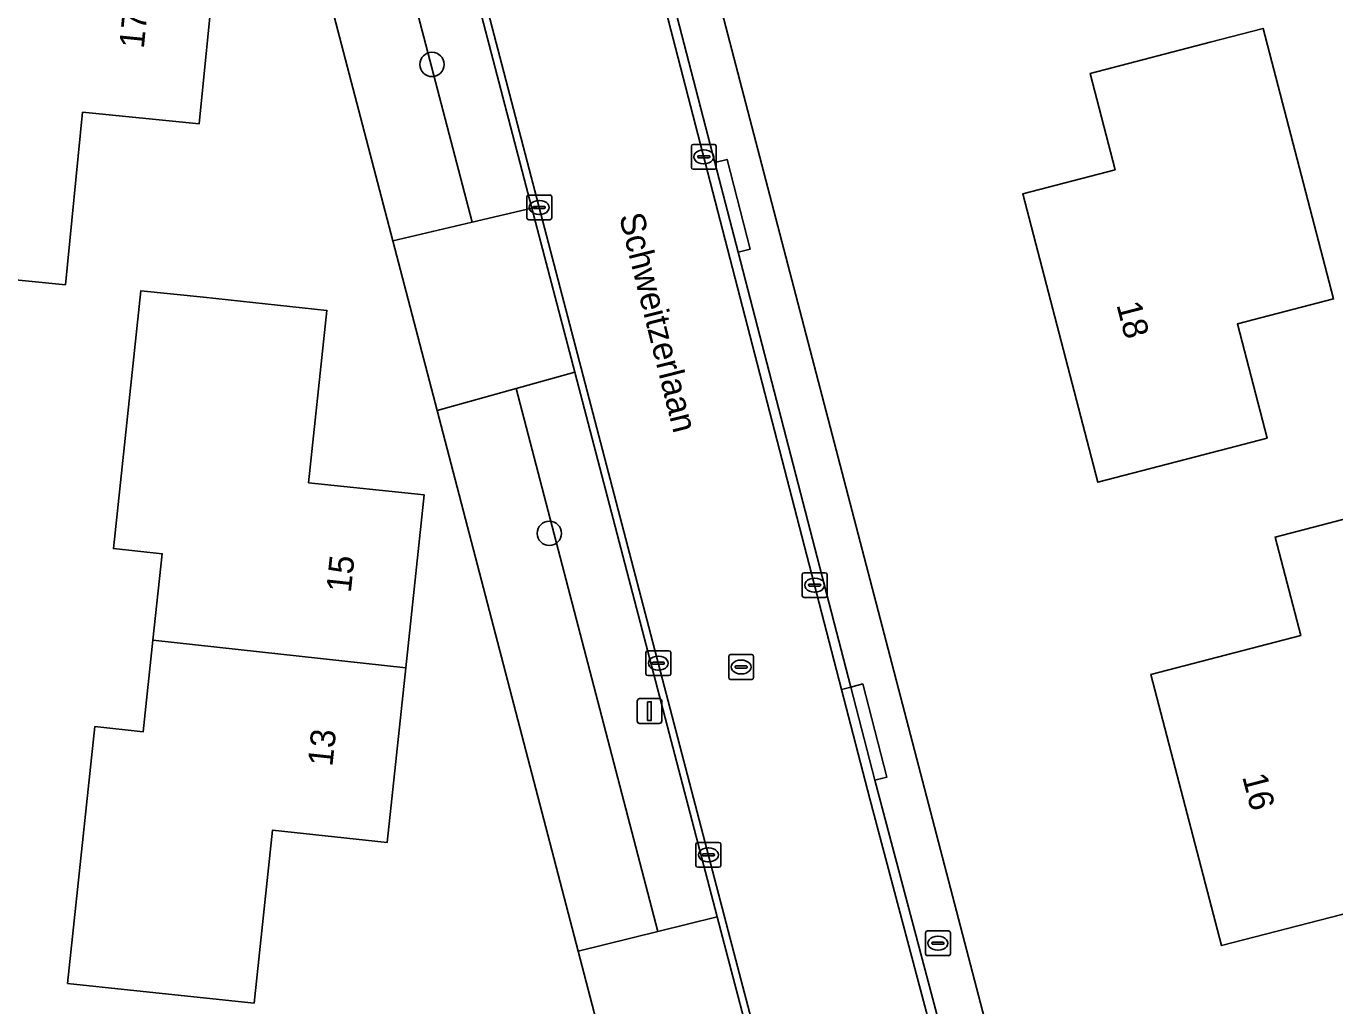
# Model space of a CAD drawing. Extents: x 162156 to 163172, y 378995 to 380779.
# Drawn here: x 162675 to 162727.7, y 380333.8 to 380373.3 of the extents above; entities that cross this region are included whole.
import ezdxf

# ---------------------------------------------------------------- set-up
doc = ezdxf.new("R2010")
doc.units = 0
for name, color, linetype in [('IMGEO_Berm_groen', 7, 'Continuous'), ('IMGEO_Boom', 7, 'Continuous'), ('IMGEO_Brandkraan', 7, 'Continuous'), ('IMGEO_Erf', 7, 'Continuous'), ('IMGEO_Groenvoorziening', 7, 'Continuous'), ('IMGEO_Kolk', 7, 'Continuous'), ('IMGEO_Lichtmast', 7, 'Continuous'), ('IMGEO_Openbare_ruimte_label', 7, 'Continuous'), ('IMGEO_Pand', 7, 'Continuous'), ('IMGEO_Pand_nummerreeks', 7, 'Continuous'), ('IMGEO_Rijbaan_lokaal_gesloten', 7, 'Continuous'), ('IMGEO_Rijbaan_lokaal_open', 7, 'Continuous'), ('IMGEO_Rioolput', 7, 'Continuous'), ('IMGEO_Voetpad_open', 7, 'Continuous')]:
    doc.layers.add(name, color=color, linetype=linetype)

msp = doc.modelspace()

# ---------------------------------------------------------------- linework, layer by layer
at = {"layer": 'IMGEO_Berm_groen'}
for points in [[(162689.559, 380388.309), (162687.169, 380387.692), (162692.998, 380365.362), (162695.408, 380365.933)], [(162697.136, 380359.32), (162694.779, 380358.663), (162700.483, 380336.783), (162702.872, 380337.376)]]:
    msp.add_lwpolyline(points, close=True, dxfattribs=at)
at = {"layer": 'IMGEO_Boom'}
for centre in [(162691.382, 380371.718), (162696.106, 380352.823)]:
    msp.add_circle(centre, 0.489, dxfattribs=at)
at = {"layer": 'IMGEO_Brandkraan'}
for p, q in [((162711.256, 380335.879), (162711.256, 380336.731)), ((162711.331, 380336.805), (162712.183, 380336.805)), ((162712.257, 380336.731), (162712.257, 380335.879)), ((162711.515, 380336.299), (162711.515, 380336.311)), ((162711.953, 380336.262), (162711.555, 380336.262)), ((162711.558, 380336.348), (162711.956, 380336.348)), ((162711.744, 380336.585), (162711.769, 380336.585)), ((162711.999, 380336.311), (162711.999, 380336.299)), ((162712.183, 380335.805), (162711.331, 380335.805)), ((162711.767, 380336.025), (162711.742, 380336.025))]:
    msp.add_line(p, q, dxfattribs=at)
for points in [[(162711.256, 380335.879), (162711.256, 380336.731)], [(162711.331, 380336.805), (162712.183, 380336.805)], [(162712.257, 380336.731), (162712.257, 380335.879)], [(162712.183, 380335.805), (162711.331, 380335.805)]]:
    msp.add_lwpolyline(points, dxfattribs=at)
for centre, radius, start, end in [((162711.333, 380336.729), 0.0765, 91.552, 178.448), ((162711.333, 380336.729), 0.0765, 91.552, 178.448), ((162712.181, 380336.729), 0.0765, 1.552, 88.448), ((162712.181, 380336.729), 0.0765, 1.552, 88.448), ((162711.555, 380336.308), 0.0403, 85.8775, 175.7526), ((162711.552, 380336.298), 0.0366, 178.938, 274.7102), ((162711.956, 380336.305), 0.043, 264.8664, 352.4533), ((162711.96, 380336.31), 0.0386, 1.7309, 96.639), ((162711.333, 380335.881), 0.0765, 181.552, 268.448), ((162711.333, 380335.881), 0.0765, 181.552, 268.448), ((162712.181, 380335.881), 0.0765, 271.552, 358.448), ((162712.181, 380335.881), 0.0765, 271.552, 358.448)]:
    msp.add_arc(centre, radius, start, end, dxfattribs=at)
for centre, major_axis, ratio, start_param, end_param in [((162711.743, 380336.305), (-0.387, 0.002), 0.722429, 4.712389, 7.853982), ((162711.768, 380336.305), (-0.39, 0.002), 0.717154, 1.570796, 4.712389)]:
    msp.add_ellipse(centre, major_axis=major_axis, ratio=ratio, start_param=start_param, end_param=end_param, dxfattribs=at)
at = {"layer": 'IMGEO_Erf'}
for points in [[(162699.109, 380328.94), (162697.271, 380335.985), (162691.587, 380357.773), (162689.804, 380364.609), (162683.996, 380386.874), (162682.226, 380393.661), (162678.892, 380406.441), (162678.13, 380409.289), (162677.305, 380412.375), (162674.933, 380424.891)], [(162692.636, 380413.099), (162695.162, 380403), (162697.063, 380396.837), (162723.095, 380296.969)], [(162672.02, 380405.962), (162676.995, 380405.469), (162676.273, 380398.182), (162677.649, 380398.046), (162676.975, 380391.25), (162676.963, 380391.126), (162679.438, 380390.881), (162678.732, 380383.751), (162683.395, 380383.289), (162682.706, 380376.334), (162682.012, 380369.325), (162677.312, 380369.791), (162676.623, 380362.843), (162671.648, 380363.336)]]:
    msp.add_lwpolyline(points, dxfattribs=at)
for points in [[(162718.198, 380354.881), (162715.173, 380366.504), (162718.892, 380367.472), (162717.881, 380371.358), (162722.72, 380372.617), (162724.85, 380373.171), (162727.687, 380362.268), (162723.814, 380361.261), (162725.013, 380356.655), (162723.105, 380356.158)], [(162677.809, 380345.037), (162679.756, 380344.83), (162680.148, 380348.522), (162680.518, 380351.998), (162678.557, 380352.206), (162679.661, 380362.601), (162682.18, 380362.334), (162687.152, 380361.806), (162686.414, 380354.864), (162691.069, 380354.37), (162690.329, 380347.408), (162689.581, 380340.366), (162684.958, 380340.857), (162684.218, 380333.891), (162679.246, 380334.419), (162676.709, 380334.688)], [(162728.015, 380337.469), (162723.172, 380336.209), (162720.329, 380347.136), (162726.366, 380348.707), (162725.334, 380352.671), (162730.173, 380353.931), (162731.189, 380354.195), (162733.064, 380346.988), (162735.063, 380339.303), (162732.141, 380338.543)]]:
    msp.add_lwpolyline(points, close=True, dxfattribs=at)
at = {"layer": 'IMGEO_Groenvoorziening'}
for points in [[(162692.998, 380365.362), (162687.169, 380387.692), (162683.996, 380386.874), (162689.804, 380364.609)], [(162700.483, 380336.783), (162694.779, 380358.663), (162691.587, 380357.773), (162697.271, 380335.985)]]:
    msp.add_lwpolyline(points, close=True, dxfattribs=at)
at = {"layer": 'IMGEO_Kolk'}
for p, q in [((162701.827, 380367.57), (162701.827, 380368.422)), ((162701.902, 380368.496), (162702.754, 380368.496)), ((162702.315, 380368.276), (162702.34, 380368.276)), ((162702.828, 380368.422), (162702.828, 380367.57)), ((162702.086, 380367.99), (162702.086, 380368.002)), ((162702.524, 380367.953), (162702.126, 380367.953)), ((162702.129, 380368.039), (162702.527, 380368.039)), ((162702.338, 380367.716), (162702.313, 380367.716)), ((162702.57, 380368.002), (162702.57, 380367.99)), ((162702.754, 380367.496), (162701.902, 380367.496)), ((162695.202, 380365.531), (162695.202, 380366.383)), ((162695.277, 380366.457), (162696.129, 380366.457)), ((162695.69, 380366.237), (162695.715, 380366.237)), ((162696.203, 380366.383), (162696.203, 380365.531)), ((162695.461, 380365.951), (162695.461, 380365.963)), ((162695.899, 380365.914), (162695.501, 380365.914)), ((162695.504, 380366), (162695.902, 380366)), ((162695.713, 380365.677), (162695.688, 380365.677)), ((162695.945, 380365.963), (162695.945, 380365.951)), ((162696.129, 380365.457), (162695.277, 380365.457)), ((162706.292, 380350.31), (162706.292, 380351.162)), ((162706.367, 380351.236), (162707.219, 380351.236)), ((162706.78, 380351.016), (162706.805, 380351.016)), ((162707.293, 380351.162), (162707.293, 380350.31)), ((162706.551, 380350.73), (162706.551, 380350.742)), ((162706.989, 380350.693), (162706.591, 380350.693)), ((162706.594, 380350.779), (162706.992, 380350.779)), ((162706.803, 380350.456), (162706.778, 380350.456)), ((162707.035, 380350.742), (162707.035, 380350.73)), ((162707.219, 380350.236), (162706.367, 380350.236)), ((162699.996, 380347.165), (162699.996, 380348.017)), ((162700.071, 380348.091), (162700.923, 380348.091)), ((162700.484, 380347.871), (162700.509, 380347.871)), ((162700.997, 380348.017), (162700.997, 380347.165)), ((162700.255, 380347.585), (162700.255, 380347.597)), ((162700.693, 380347.548), (162700.295, 380347.548)), ((162700.298, 380347.634), (162700.696, 380347.634)), ((162700.507, 380347.311), (162700.482, 380347.311)), ((162700.739, 380347.597), (162700.739, 380347.585)), ((162700.923, 380347.091), (162700.071, 380347.091)), ((162702.087, 380340.367), (162702.939, 380340.367)), ((162702.012, 380339.441), (162702.012, 380340.293)), ((162702.271, 380339.861), (162702.271, 380339.873)), ((162702.709, 380339.824), (162702.311, 380339.824)), ((162702.314, 380339.91), (162702.712, 380339.91)), ((162702.5, 380340.147), (162702.525, 380340.147)), ((162702.755, 380339.873), (162702.755, 380339.861)), ((162703.013, 380340.293), (162703.013, 380339.441)), ((162702.939, 380339.367), (162702.087, 380339.367)), ((162702.523, 380339.587), (162702.498, 380339.587))]:
    msp.add_line(p, q, dxfattribs=at)
for points in [[(162701.827, 380367.57), (162701.827, 380368.422)], [(162701.902, 380368.496), (162702.754, 380368.496)], [(162702.828, 380368.422), (162702.828, 380367.57)], [(162702.754, 380367.496), (162701.902, 380367.496)], [(162695.202, 380365.531), (162695.202, 380366.383)], [(162695.277, 380366.457), (162696.129, 380366.457)], [(162696.203, 380366.383), (162696.203, 380365.531)], [(162696.129, 380365.457), (162695.277, 380365.457)], [(162706.292, 380350.31), (162706.292, 380351.162)], [(162706.367, 380351.236), (162707.219, 380351.236)], [(162707.293, 380351.162), (162707.293, 380350.31)], [(162707.219, 380350.236), (162706.367, 380350.236)], [(162699.996, 380347.165), (162699.996, 380348.017)], [(162700.071, 380348.091), (162700.923, 380348.091)], [(162700.997, 380348.017), (162700.997, 380347.165)], [(162700.923, 380347.091), (162700.071, 380347.091)], [(162702.087, 380340.367), (162702.939, 380340.367)], [(162702.012, 380339.441), (162702.012, 380340.293)], [(162703.013, 380340.293), (162703.013, 380339.441)], [(162702.939, 380339.367), (162702.087, 380339.367)]]:
    msp.add_lwpolyline(points, dxfattribs=at)
for centre, radius, start, end in [((162701.904, 380368.42), 0.0765, 91.552, 178.448), ((162701.904, 380368.42), 0.0765, 91.552, 178.448), ((162702.752, 380368.42), 0.0765, 1.552, 88.448), ((162702.752, 380368.42), 0.0765, 1.552, 88.448), ((162702.126, 380367.999), 0.0403, 85.8775, 175.7526), ((162702.123, 380367.989), 0.0366, 178.938, 274.7102), ((162702.527, 380367.996), 0.043, 264.8664, 352.4533), ((162702.531, 380368.001), 0.0386, 1.7309, 96.639), ((162701.904, 380367.572), 0.0765, 181.552, 268.448), ((162701.904, 380367.572), 0.0765, 181.552, 268.448), ((162702.752, 380367.572), 0.0765, 271.552, 358.448), ((162702.752, 380367.572), 0.0765, 271.552, 358.448), ((162695.279, 380366.381), 0.0765, 91.552, 178.448), ((162695.279, 380366.381), 0.0765, 91.552, 178.448), ((162696.127, 380366.381), 0.0765, 1.552, 88.448), ((162696.127, 380366.381), 0.0765, 1.552, 88.448), ((162695.501, 380365.96), 0.0403, 85.8775, 175.7526), ((162695.498, 380365.95), 0.0366, 178.938, 274.7102), ((162695.902, 380365.957), 0.043, 264.8664, 352.4533), ((162695.906, 380365.962), 0.0386, 1.7309, 96.639), ((162695.279, 380365.533), 0.0765, 181.552, 268.448), ((162695.279, 380365.533), 0.0765, 181.552, 268.448), ((162696.127, 380365.533), 0.0765, 271.552, 358.448), ((162696.127, 380365.533), 0.0765, 271.552, 358.448), ((162706.369, 380351.16), 0.0765, 91.552, 178.448), ((162706.369, 380351.16), 0.0765, 91.552, 178.448), ((162707.217, 380351.16), 0.0765, 1.552, 88.448), ((162707.217, 380351.16), 0.0765, 1.552, 88.448), ((162706.369, 380350.312), 0.0765, 181.552, 268.448), ((162706.369, 380350.312), 0.0765, 181.552, 268.448), ((162706.591, 380350.739), 0.0403, 85.8775, 175.7526), ((162706.588, 380350.729), 0.0366, 178.938, 274.7102), ((162706.992, 380350.736), 0.043, 264.8664, 352.4533), ((162706.996, 380350.741), 0.0386, 1.7309, 96.639), ((162707.217, 380350.312), 0.0765, 271.552, 358.448), ((162707.217, 380350.312), 0.0765, 271.552, 358.448), ((162700.073, 380348.015), 0.0765, 91.552, 178.448), ((162700.073, 380348.015), 0.0765, 91.552, 178.448), ((162700.921, 380348.015), 0.0765, 1.552, 88.448), ((162700.921, 380348.015), 0.0765, 1.552, 88.448), ((162700.073, 380347.167), 0.0765, 181.552, 268.448), ((162700.073, 380347.167), 0.0765, 181.552, 268.448), ((162700.295, 380347.594), 0.0403, 85.8775, 175.7526), ((162700.292, 380347.584), 0.0366, 178.938, 274.7102), ((162700.696, 380347.591), 0.043, 264.8664, 352.4533), ((162700.7, 380347.596), 0.0386, 1.7309, 96.639), ((162700.921, 380347.167), 0.0765, 271.552, 358.448), ((162700.921, 380347.167), 0.0765, 271.552, 358.448), ((162702.089, 380340.291), 0.0765, 91.552, 178.448), ((162702.089, 380340.291), 0.0765, 91.552, 178.448), ((162702.937, 380340.291), 0.0765, 1.552, 88.448), ((162702.937, 380340.291), 0.0765, 1.552, 88.448), ((162702.311, 380339.87), 0.0403, 85.8775, 175.7526), ((162702.308, 380339.86), 0.0366, 178.938, 274.7102), ((162702.712, 380339.867), 0.043, 264.8664, 352.4533), ((162702.716, 380339.872), 0.0386, 1.7309, 96.639), ((162702.089, 380339.443), 0.0765, 181.552, 268.448), ((162702.089, 380339.443), 0.0765, 181.552, 268.448), ((162702.937, 380339.443), 0.0765, 271.552, 358.448), ((162702.937, 380339.443), 0.0765, 271.552, 358.448)]:
    msp.add_arc(centre, radius, start, end, dxfattribs=at)
for centre, major_axis, ratio, start_param, end_param in [((162702.314, 380367.996), (-0.387, 0.002), 0.722429, 4.712389, 7.853982), ((162702.339, 380367.996), (-0.39, 0.002), 0.717154, 1.570796, 4.712389), ((162695.689, 380365.957), (-0.387, 0.002), 0.722429, 4.712389, 7.853982), ((162695.714, 380365.957), (-0.39, 0.002), 0.717154, 1.570796, 4.712389), ((162706.779, 380350.736), (-0.387, 0.002), 0.722429, 4.712389, 7.853982), ((162706.804, 380350.736), (-0.39, 0.002), 0.717154, 1.570796, 4.712389), ((162700.483, 380347.591), (-0.387, 0.002), 0.722429, 4.712389, 7.853982), ((162700.508, 380347.591), (-0.39, 0.002), 0.717154, 1.570796, 4.712389), ((162702.499, 380339.867), (-0.387, 0.002), 0.722429, 4.712389, 7.853982), ((162702.524, 380339.867), (-0.39, 0.002), 0.717154, 1.570796, 4.712389)]:
    msp.add_ellipse(centre, major_axis=major_axis, ratio=ratio, start_param=start_param, end_param=end_param, dxfattribs=at)
at = {"layer": 'IMGEO_Lichtmast'}
for p, q in [((162699.745, 380346.162), (162700.535, 380346.162)), ((162700.535, 380346.162), (162699.745, 380346.162)), ((162699.645, 380345.262), (162699.645, 380346.062)), ((162699.645, 380346.062), (162699.645, 380345.262)), ((162700.635, 380346.062), (162700.635, 380345.262)), ((162700.635, 380345.262), (162700.635, 380346.062)), ((162700.535, 380345.162), (162699.745, 380345.162)), ((162699.745, 380345.162), (162700.535, 380345.162))]:
    msp.add_line(p, q, dxfattribs=at)
msp.add_lwpolyline([(162700.065, 380346.037), (162700.215, 380346.037), (162700.215, 380345.287), (162700.065, 380345.287), (162700.065, 380346.037)], dxfattribs=at)
for centre, start, end in [((162699.745, 380346.062), 90, 180), ((162699.745, 380346.062), 90, 180), ((162700.535, 380346.062), 0, 90), ((162700.535, 380346.062), 360, 90), ((162699.745, 380345.262), 180, 270), ((162699.745, 380345.262), 180, 270), ((162700.535, 380345.262), 270, 0), ((162700.535, 380345.262), 270, 0)]:
    msp.add_arc(centre, 0.1, start, end, dxfattribs=at)
at = {"layer": 'IMGEO_Pand'}
for points in [[(162682.706, 380376.334), (162672.513, 380377.454), (162672.142, 380373.712), (162670.157, 380373.909), (162669.135, 380363.585), (162671.648, 380363.336), (162676.623, 380362.843), (162677.312, 380369.791), (162682.012, 380369.325)], [(162723.105, 380356.158), (162725.013, 380356.655), (162723.814, 380361.261), (162727.687, 380362.268), (162724.85, 380373.171), (162722.72, 380372.617), (162717.881, 380371.358), (162718.892, 380367.472), (162715.173, 380366.504), (162718.198, 380354.881)], [(162680.148, 380348.522), (162690.329, 380347.408), (162691.069, 380354.37), (162686.414, 380354.864), (162687.152, 380361.806), (162682.18, 380362.334), (162679.661, 380362.601), (162678.557, 380352.206), (162680.518, 380351.998)], [(162732.141, 380338.543), (162735.063, 380339.303), (162733.064, 380346.988), (162731.189, 380354.195), (162730.173, 380353.931), (162725.334, 380352.671), (162726.366, 380348.707), (162720.329, 380347.136), (162723.172, 380336.209), (162728.015, 380337.469)], [(162680.148, 380348.522), (162679.756, 380344.83), (162677.809, 380345.037), (162676.709, 380334.688), (162679.246, 380334.419), (162684.218, 380333.891), (162684.958, 380340.857), (162689.581, 380340.366), (162690.329, 380347.408)]]:
    msp.add_lwpolyline(points, close=True, dxfattribs=at)
at = {"layer": 'IMGEO_Rijbaan_lokaal_gesloten'}
for points in [[(162680.525, 380429.323), (162678.724, 380445.517), (162678.557, 380447.491), (162678.535, 380447.716), (162678.198, 380447.57), (162678.473, 380445.123), (162680.83, 380423.933), (162681.587, 380419.614), (162682.894, 380413.81), (162683.705, 380410.707), (162687.775, 380395.136), (162689.559, 380388.309), (162695.408, 380365.933), (162695.691, 380366.007), (162690.83, 380384.632)], [(162684.572, 380408.676), (162690.83, 380384.632), (162695.691, 380366.007), (162703.622, 380335.621), (162710.51, 380309.391), (162714.578, 380294.078), (162716.187, 380288.023)], [(162725.252, 380276.334), (162722.054, 380292.949), (162721.262, 380295.939), (162709.02, 380342.123), (162707.879, 380346.533), (162696.902, 380388.967), (162691.62, 380408.754)], [(162716.187, 380288.023), (162714.578, 380294.078), (162710.51, 380309.391), (162703.622, 380335.621), (162695.691, 380366.007), (162695.408, 380365.933), (162697.136, 380359.32), (162702.872, 380337.376), (162704.706, 380330.361), (162710.289, 380309), (162714.231, 380293.981), (162715.822, 380287.919)]]:
    msp.add_lwpolyline(points, dxfattribs=at)
at = {"layer": 'IMGEO_Rijbaan_lokaal_open'}
for points in [[(162703.711, 380364.149), (162702.774, 380367.765), (162699.254, 380381.363), (162698.306, 380385.024), (162697.814, 380386.924), (162697.261, 380389.061), (162696.866, 380390.533), (162692.928, 380405.226), (162691.958, 380408.844), (162691.381, 380411.149)], [(162691.62, 380408.754), (162696.902, 380388.967), (162707.879, 380346.533), (162708.247, 380346.628), (162703.711, 380364.149)], [(162722.533, 380292.763), (162721.626, 380296.04), (162721.481, 380296.587), (162719.109, 380305.536), (162714.195, 380324.082), (162713.217, 380327.771), (162709.388, 380342.219), (162709.218, 380342.874), (162708.247, 380346.628), (162707.879, 380346.533), (162709.02, 380342.123), (162721.262, 380295.939), (162722.054, 380292.949), (162725.252, 380276.334)]]:
    msp.add_lwpolyline(points, dxfattribs=at)
at = {"layer": 'IMGEO_Rioolput'}
for p, q in [((162703.332, 380347.011), (162703.332, 380347.863)), ((162703.407, 380347.937), (162704.259, 380347.937)), ((162703.82, 380347.717), (162703.845, 380347.717)), ((162704.333, 380347.863), (162704.333, 380347.011)), ((162703.591, 380347.431), (162703.591, 380347.443)), ((162704.029, 380347.394), (162703.631, 380347.394)), ((162703.634, 380347.48), (162704.032, 380347.48)), ((162703.843, 380347.157), (162703.818, 380347.157)), ((162704.075, 380347.443), (162704.075, 380347.431)), ((162704.259, 380346.937), (162703.407, 380346.937))]:
    msp.add_line(p, q, dxfattribs=at)
for points in [[(162703.332, 380347.011), (162703.332, 380347.863)], [(162703.407, 380347.937), (162704.259, 380347.937)], [(162704.333, 380347.863), (162704.333, 380347.011)], [(162704.259, 380346.937), (162703.407, 380346.937)]]:
    msp.add_lwpolyline(points, dxfattribs=at)
for centre, radius, start, end in [((162703.409, 380347.861), 0.0765, 91.552, 178.448), ((162703.409, 380347.861), 0.0765, 91.552, 178.448), ((162704.257, 380347.861), 0.0765, 1.552, 88.448), ((162704.257, 380347.861), 0.0765, 1.552, 88.448), ((162703.631, 380347.44), 0.0403, 85.8775, 175.7526), ((162703.628, 380347.43), 0.0366, 178.938, 274.7102), ((162704.032, 380347.437), 0.043, 264.8664, 352.4533), ((162704.036, 380347.442), 0.0386, 1.7309, 96.639), ((162703.409, 380347.013), 0.0765, 181.552, 268.448), ((162703.409, 380347.013), 0.0765, 181.552, 268.448), ((162704.257, 380347.013), 0.0765, 271.552, 358.448), ((162704.257, 380347.013), 0.0765, 271.552, 358.448)]:
    msp.add_arc(centre, radius, start, end, dxfattribs=at)
for centre, major_axis, ratio, start_param, end_param in [((162703.819, 380347.437), (-0.387, 0.002), 0.722429, 4.712389, 7.853982), ((162703.844, 380347.437), (-0.39, 0.002), 0.717154, 1.570796, 4.712389)]:
    msp.add_ellipse(centre, major_axis=major_axis, ratio=ratio, start_param=start_param, end_param=end_param, dxfattribs=at)
at = {"layer": 'IMGEO_Voetpad_open'}
for points in [[(162723.095, 380296.969), (162697.063, 380396.837)], [(162699.254, 380381.363), (162702.774, 380367.765), (162703.263, 380367.891), (162704.199, 380364.275), (162703.711, 380364.149), (162708.247, 380346.628), (162708.731, 380346.753), (162709.702, 380342.999), (162709.218, 380342.874), (162709.388, 380342.219), (162713.217, 380327.771)]]:
    msp.add_lwpolyline(points, dxfattribs=at)
for points in [[(162702.774, 380367.765), (162703.711, 380364.149), (162704.199, 380364.275), (162703.263, 380367.891)], [(162697.136, 380359.32), (162695.408, 380365.933), (162692.998, 380365.362), (162689.804, 380364.609), (162691.587, 380357.773), (162694.779, 380358.663)], [(162708.247, 380346.628), (162709.218, 380342.874), (162709.702, 380342.999), (162708.731, 380346.753)], [(162702.307, 380329.752), (162704.706, 380330.361), (162702.872, 380337.376), (162700.483, 380336.783), (162697.271, 380335.985), (162699.109, 380328.94)]]:
    msp.add_lwpolyline(points, close=True, dxfattribs=at)

# ---------------------------------------------------------------- texts
at = {"layer": 'IMGEO_Openbare_ruimte_label'}
msp.add_text('Schweitzerlaan', height=1, rotation=284.1196, dxfattribs=at).set_placement((162698.911, 380365.605))
at = {"layer": 'IMGEO_Pand_nummerreeks'}
for s, rotation, p in [('17', 84.3439, (162679.777, 380372.333)), ('18', 284.5882, (162718.939, 380362.036)), ('15', 83.9348, (162688.113, 380350.404)), ('13', 83.9348, (162687.369, 380343.402)), ('16', 284.5839, (162724.004, 380343.019))]:
    msp.add_text(s, height=1, rotation=rotation, dxfattribs=at).set_placement(p)

doc.saveas('drawing.dxf')
